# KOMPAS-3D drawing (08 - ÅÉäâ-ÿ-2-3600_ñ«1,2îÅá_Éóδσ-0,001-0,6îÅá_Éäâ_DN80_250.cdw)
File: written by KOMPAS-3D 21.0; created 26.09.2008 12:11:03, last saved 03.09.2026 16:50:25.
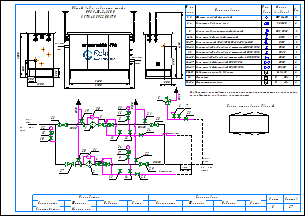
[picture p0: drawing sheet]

Sheets 1-2: A3, landscape

Document properties: Наименование: Макро:21; Автор: RaskoAdmin; Форматы листов документа: 2xA3; Полное имя файла: \\UR38nt01\Departments\КТО\КБ ПУРДГ\Заявки\Прайс-лист на типовые шкафы ГРПШ\ПРДГ_стандарт_20_03_2026\ПРДГ с РДГ(Н, В)\ПРДГ-Ш-2-3600_до1,2МПа_Рвых-0,001-0,6МПа_РДГ_DN80_250.cdw

Title block, sheet 1: Наименование: Пункт учета газа / ПУГ-Ш-400-Р / ЛГТИ.485922.001ТУ; designation: ЛГТИ.03.4411141; sheet number: 1; Количество листов документа: 2; organisation: ООО "ЭЛЬСТЕР Газэлектроника"; Форматы листов документа: A3; stored path: C:\Рабочие документы\Компас\ПУГ\Схема.cdw; Разработал: Устинов; Проверил: Кошкин; Утвердил: Кошкин
Title block, sheet 2: sheet number: 2; stored path: D:\Рабочие документы\Заявки\ПУРДГ\ПУРДГ-ШУЭО-2-100-Р 4411220.cdw; designation, second copy: ЛГТИ.03.4411141-

Views: Вид 1, Вид 2
Referenced files: wcvoit.frw
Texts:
  Normal
  № на
  схеме
  Усл.
  обозн.
  Марка
  (модель)
  Кол.
  Фильтр газовый фланцевый
  ФГ 16-80
  Регулятор давления газа
  РДГ-50
  Клапан предохранительный сбросной
  ПСК DN25
  Кран шаровой газовый латунный
  DN15
  Кран кнопочный VE-РАСКО-НЗ-1,6-G1/2-М20
  Кран шаровой "под приварку" штуцерный DN20 PN16
  Кран шаровой "под приварку" штуцерный DN25 PN16
  Кран шаровой "под приварку" штуцерный п/п DN20 PN16
  DN20
  DN25
  Кран шаровой фланцевый DN80 PN16
  Кран шаровой фланцевый DN250 PN16
  DN80
  DN250
  Индикатор перепада давления
  Delta 15
  Манометр
  Манометр-напоромер
  0...     МПа
  0...     кПа
  Общий вид и габариты шкафа
  ПРДГ-Ш-2-3600
  Выход газа
  Вход газа
  Схема открывания дверей
  logo-rasko-ge.png
  Предприятие изготовитель может заменять комплектующие на аналогичные,
  не ухудшающие заявленных характеристик.
  Вход
  газа
  PDI
  Выход
  Р=     кПа
  Импульс DN20
  ≥5DN
  HYSWLongFangSong
  Р=       МПа
  Должность
  Конструктор
  Фамилия
  Подпись
  Дата
  Согласовано
  Максимкин
  Лист
  Листов
  POLYLINE_STYLE_0.18_RGB_0_0_0
  POLYLINE_STYLE_0.50_RGB_0_0_0
  POLYLINE_STYLE_0.34_RGB_0_0_0
  PHANTOM_RGB_0_0_0_SC_1_THICK_0.18
  K5LT_THIN_RGB_0_0_0_THICK_0.18
  K5LT32769_RGB_0_0_0_THICK_0.18
  K5LT12_RGB_0_0_0_SC_1_THICK_0.18
  K5LT_DASHED_RGB_0_0_0_SC_1_THICK_0.18
  ACISOTGL_RGB_0_0_0_SC_0.8_THICK_0.25
  CONTINUOUS_RGB_0_127_31_THICK_0.3
  CONTINUOUS_RGB_0_0_255_THICK_0.35
  CONTINUOUS_RGB_255_0_0_THICK_0.35
  POLYLINE_STYLE_0.25_RGB_0_0_0
  CONTINUOUS_RGB_0_0_0_THICK_0.5
  POLYLINE_STYLE_0.35_RGB_0_0_255
  CONTINUOUS_RGB_0_0_0_THICK_0.4
  CONTINUOUS_RGB_0_0_0_THICK_0.35
  Без оформления
Dimensions and other numbers on the sheet: 1; 1, 2; 2; 3, 4; 5; 6-14; 9; 15-17; 3; 18-22; 23; 24-25; 26-27; 28-29; 30-31; 32; 33-34; 500; 1200; 305; 2000; 3900; 4130; 3600; 4; 10; 27; 28; 29; 8; 12; 19; 20; 21; 22; 25; 24; 30; 31; 15; 16; 26; 6; 7; 11; 14; 13; 33; 17; 34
